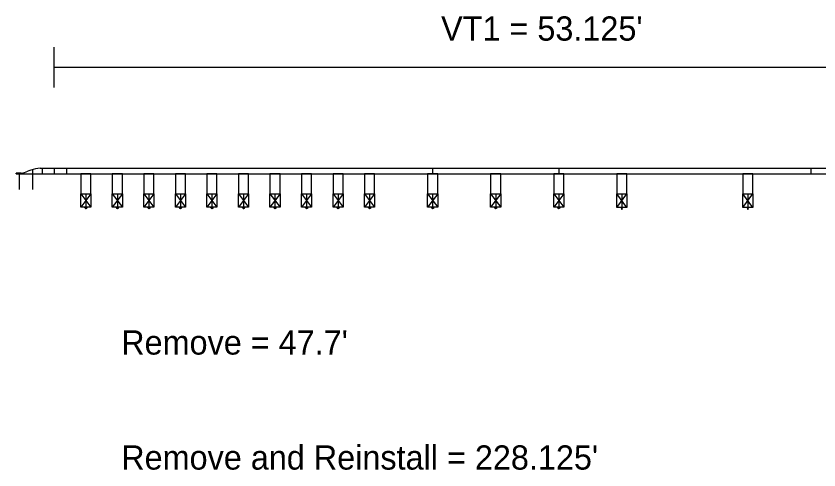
# Model space of a CAD drawing. Extents: x 16537443 to 16538473, y 7054586 to 7055469.
# Drawn here: x 16538169.69 to 16538209.48, y 7055402.88 to 7055425.37 of the extents above; entities that cross this region are included whole.
import ezdxf

# ---------------------------------------------------------------- set-up
doc = ezdxf.new("R2010")
doc.units = 0
doc.layers.add('Draft_DNC', color=7, linetype='Continuous')

msp = doc.modelspace()

# ---------------------------------------------------------------- linework, layer by layer
at = {"layer": 'Draft_DNC'}
for p, q in [((16538171.587, 7055421.832), (16538171.587, 7055423.832)), ((16538171.587, 7055422.832), (16538224.712, 7055422.833)), ((16538169.941, 7055417.587), (16538169.691, 7055417.587)), ((16538169.691, 7055417.561), (16538169.691, 7055417.587)), ((16538169.691, 7055417.561), (16538209.087, 7055417.561)), ((16538169.857, 7055416.77), (16538169.857, 7055417.588)), ((16538170.424, 7055417.739), (16538170.281, 7055417.683)), ((16538170.524, 7055416.77), (16538170.524, 7055417.772)), ((16538170.886, 7055417.832), (16538209.087, 7055417.832)), ((16538170.982, 7055417.832), (16538196.587, 7055417.832)), ((16538170.982, 7055417.832), (16538170.982, 7055417.561)), ((16538171.587, 7055417.832), (16538171.587, 7055417.561)), ((16538172.191, 7055417.832), (16538172.191, 7055417.561)), ((16538173.399, 7055417.561), (16538172.899, 7055417.561)), ((16538172.899, 7055417.561), (16538172.899, 7055416.562)), ((16538173.399, 7055416.562), (16538173.399, 7055417.561)), ((16538174.962, 7055417.561), (16538174.462, 7055417.561)), ((16538174.462, 7055417.561), (16538174.462, 7055416.562)), ((16538174.962, 7055416.562), (16538174.962, 7055417.561)), ((16538176.524, 7055417.561), (16538176.024, 7055417.561)), ((16538176.024, 7055417.561), (16538176.024, 7055416.562)), ((16538176.524, 7055416.562), (16538176.524, 7055417.561)), ((16538178.087, 7055417.561), (16538177.587, 7055417.561)), ((16538177.587, 7055417.561), (16538177.587, 7055416.562)), ((16538178.087, 7055416.562), (16538178.087, 7055417.561)), ((16538179.649, 7055417.561), (16538179.149, 7055417.561)), ((16538179.149, 7055417.561), (16538179.149, 7055416.562)), ((16538179.649, 7055416.562), (16538179.649, 7055417.561)), ((16538181.212, 7055417.561), (16538180.712, 7055417.561)), ((16538180.712, 7055417.561), (16538180.712, 7055416.562)), ((16538181.212, 7055416.562), (16538181.212, 7055417.561)), ((16538182.774, 7055417.561), (16538182.274, 7055417.561)), ((16538182.274, 7055417.561), (16538182.274, 7055416.562)), ((16538182.774, 7055416.562), (16538182.774, 7055417.561)), ((16538184.337, 7055417.561), (16538183.837, 7055417.561)), ((16538183.837, 7055417.561), (16538183.837, 7055416.562)), ((16538184.337, 7055417.561), (16538183.837, 7055417.561)), ((16538183.837, 7055417.561), (16538183.837, 7055416.562)), ((16538184.337, 7055416.562), (16538184.337, 7055417.561)), ((16538184.337, 7055416.562), (16538184.337, 7055417.561)), ((16538185.899, 7055417.561), (16538185.399, 7055417.561)), ((16538185.399, 7055417.561), (16538185.399, 7055416.562)), ((16538185.899, 7055416.562), (16538185.899, 7055417.561)), ((16538187.462, 7055417.561), (16538186.962, 7055417.561)), ((16538186.962, 7055417.561), (16538186.962, 7055416.562)), ((16538187.462, 7055416.562), (16538187.462, 7055417.561)), ((16538190.587, 7055417.561), (16538190.087, 7055417.561)), ((16538190.087, 7055417.561), (16538190.087, 7055416.562)), ((16538190.337, 7055417.832), (16538190.337, 7055417.561)), ((16538190.587, 7055416.562), (16538190.587, 7055417.561)), ((16538193.712, 7055417.561), (16538193.212, 7055417.561)), ((16538193.212, 7055417.561), (16538193.212, 7055416.562)), ((16538193.712, 7055416.562), (16538193.712, 7055417.561)), ((16538196.837, 7055417.561), (16538196.337, 7055417.561)), ((16538196.337, 7055417.561), (16538196.337, 7055416.562)), ((16538196.587, 7055417.832), (16538196.587, 7055417.561)), ((16538196.837, 7055416.562), (16538196.837, 7055417.561)), ((16538199.962, 7055417.561), (16538199.462, 7055417.561)), ((16538199.462, 7055417.561), (16538199.462, 7055416.561)), ((16538199.962, 7055416.561), (16538199.962, 7055417.561)), ((16538206.212, 7055417.561), (16538205.712, 7055417.561)), ((16538205.712, 7055417.561), (16538205.712, 7055416.561)), ((16538206.212, 7055416.561), (16538206.212, 7055417.561)), ((16538209.087, 7055417.832), (16538209.087, 7055417.561)), ((16538209.087, 7055417.832), (16538221.587, 7055417.832)), ((16538209.087, 7055417.832), (16538209.087, 7055417.561)), ((16538209.087, 7055417.561), (16538221.587, 7055417.561)), ((16538172.899, 7055416.562), (16538173.399, 7055416.562)), ((16538173.399, 7055416.562), (16538172.899, 7055415.895)), ((16538172.899, 7055416.562), (16538173.399, 7055415.895)), ((16538173.149, 7055416.562), (16538173.149, 7055415.895)), ((16538174.462, 7055416.562), (16538174.962, 7055416.562)), ((16538174.962, 7055416.562), (16538174.462, 7055415.895)), ((16538174.462, 7055416.562), (16538174.962, 7055415.895)), ((16538174.712, 7055416.562), (16538174.712, 7055415.895)), ((16538176.024, 7055416.562), (16538176.524, 7055416.562)), ((16538176.524, 7055416.562), (16538176.024, 7055415.895)), ((16538176.024, 7055416.562), (16538176.524, 7055415.895)), ((16538176.274, 7055416.562), (16538176.274, 7055415.895)), ((16538177.587, 7055416.562), (16538178.087, 7055416.562)), ((16538178.087, 7055416.562), (16538177.587, 7055415.895)), ((16538177.587, 7055416.562), (16538178.087, 7055415.895)), ((16538177.837, 7055416.562), (16538177.837, 7055415.895)), ((16538179.149, 7055416.562), (16538179.649, 7055416.562)), ((16538179.649, 7055416.562), (16538179.149, 7055415.895)), ((16538179.149, 7055416.562), (16538179.649, 7055415.895)), ((16538179.399, 7055416.562), (16538179.399, 7055415.895)), ((16538180.712, 7055416.562), (16538181.212, 7055416.562)), ((16538181.212, 7055416.562), (16538180.712, 7055415.895)), ((16538180.712, 7055416.562), (16538181.212, 7055415.895)), ((16538180.962, 7055416.562), (16538180.962, 7055415.895)), ((16538182.274, 7055416.562), (16538182.774, 7055416.562)), ((16538182.774, 7055416.562), (16538182.274, 7055415.895)), ((16538182.274, 7055416.562), (16538182.774, 7055415.895)), ((16538182.524, 7055416.562), (16538182.524, 7055415.895)), ((16538183.837, 7055416.562), (16538184.337, 7055416.562)), ((16538183.837, 7055416.562), (16538184.337, 7055416.562)), ((16538184.337, 7055416.562), (16538183.837, 7055415.895)), ((16538183.837, 7055416.562), (16538184.337, 7055415.895)), ((16538184.087, 7055416.562), (16538184.087, 7055415.895)), ((16538185.399, 7055416.562), (16538185.899, 7055416.562)), ((16538185.899, 7055416.562), (16538185.399, 7055415.895)), ((16538185.399, 7055416.562), (16538185.899, 7055415.895)), ((16538185.649, 7055416.562), (16538185.649, 7055415.895)), ((16538186.962, 7055416.562), (16538187.462, 7055416.562)), ((16538187.462, 7055416.562), (16538186.962, 7055415.895)), ((16538186.962, 7055416.562), (16538187.462, 7055415.895)), ((16538187.212, 7055416.562), (16538187.212, 7055415.895)), ((16538190.087, 7055416.562), (16538190.587, 7055416.562)), ((16538190.587, 7055416.562), (16538190.087, 7055415.895)), ((16538190.087, 7055416.562), (16538190.587, 7055415.895)), ((16538190.337, 7055416.562), (16538190.337, 7055415.895)), ((16538193.212, 7055416.562), (16538193.712, 7055416.562)), ((16538193.712, 7055416.562), (16538193.212, 7055415.895)), ((16538193.212, 7055416.562), (16538193.712, 7055415.895)), ((16538193.462, 7055416.562), (16538193.462, 7055415.895)), ((16538196.337, 7055416.562), (16538196.837, 7055416.562)), ((16538196.837, 7055416.562), (16538196.337, 7055415.895)), ((16538196.337, 7055416.562), (16538196.837, 7055415.895)), ((16538196.587, 7055416.562), (16538196.587, 7055415.895)), ((16538199.462, 7055416.561), (16538199.962, 7055416.561)), ((16538199.462, 7055415.894), (16538199.962, 7055416.561)), ((16538199.962, 7055415.894), (16538199.462, 7055416.561)), ((16538199.712, 7055416.561), (16538199.712, 7055415.894)), ((16538205.712, 7055416.561), (16538206.212, 7055416.561)), ((16538205.712, 7055415.894), (16538206.212, 7055416.561)), ((16538206.212, 7055415.894), (16538205.712, 7055416.561)), ((16538205.962, 7055416.561), (16538205.962, 7055415.894)), ((16538173.399, 7055415.895), (16538172.899, 7055415.895)), ((16538173.069, 7055415.895), (16538173.069, 7055415.879)), ((16538173.229, 7055415.895), (16538173.229, 7055415.879)), ((16538174.962, 7055415.895), (16538174.462, 7055415.895)), ((16538174.632, 7055415.895), (16538174.632, 7055415.879)), ((16538174.792, 7055415.895), (16538174.792, 7055415.879)), ((16538176.524, 7055415.895), (16538176.024, 7055415.895)), ((16538176.194, 7055415.895), (16538176.194, 7055415.879)), ((16538176.354, 7055415.895), (16538176.354, 7055415.879)), ((16538178.087, 7055415.895), (16538177.587, 7055415.895)), ((16538177.757, 7055415.895), (16538177.757, 7055415.879)), ((16538177.917, 7055415.895), (16538177.917, 7055415.879)), ((16538179.649, 7055415.895), (16538179.149, 7055415.895)), ((16538179.319, 7055415.895), (16538179.319, 7055415.879)), ((16538179.479, 7055415.895), (16538179.479, 7055415.879)), ((16538181.212, 7055415.895), (16538180.712, 7055415.895)), ((16538180.882, 7055415.895), (16538180.882, 7055415.879)), ((16538181.042, 7055415.895), (16538181.042, 7055415.879)), ((16538182.774, 7055415.895), (16538182.274, 7055415.895)), ((16538182.444, 7055415.895), (16538182.444, 7055415.879)), ((16538182.604, 7055415.895), (16538182.604, 7055415.879)), ((16538184.337, 7055415.895), (16538183.837, 7055415.895)), ((16538184.007, 7055415.895), (16538184.007, 7055415.879)), ((16538184.167, 7055415.895), (16538184.167, 7055415.879)), ((16538185.899, 7055415.895), (16538185.399, 7055415.895)), ((16538185.569, 7055415.895), (16538185.569, 7055415.879)), ((16538185.729, 7055415.895), (16538185.729, 7055415.879)), ((16538187.462, 7055415.895), (16538186.962, 7055415.895)), ((16538187.132, 7055415.895), (16538187.132, 7055415.879)), ((16538187.292, 7055415.895), (16538187.292, 7055415.879)), ((16538190.587, 7055415.895), (16538190.087, 7055415.895)), ((16538190.257, 7055415.895), (16538190.257, 7055415.879)), ((16538190.417, 7055415.895), (16538190.417, 7055415.879)), ((16538193.712, 7055415.895), (16538193.212, 7055415.895)), ((16538193.382, 7055415.895), (16538193.382, 7055415.879)), ((16538193.542, 7055415.895), (16538193.542, 7055415.879)), ((16538196.837, 7055415.895), (16538196.337, 7055415.895)), ((16538196.507, 7055415.895), (16538196.507, 7055415.879)), ((16538196.667, 7055415.895), (16538196.667, 7055415.879)), ((16538173.229, 7055415.879), (16538173.069, 7055415.879)), ((16538173.109, 7055415.879), (16538173.109, 7055415.841)), ((16538173.189, 7055415.841), (16538173.109, 7055415.841)), ((16538173.125, 7055415.879), (16538173.125, 7055415.841)), ((16538173.139, 7055415.841), (16538173.139, 7055415.812)), ((16538173.159, 7055415.812), (16538173.139, 7055415.812)), ((16538173.159, 7055415.841), (16538173.159, 7055415.812)), ((16538173.173, 7055415.879), (16538173.173, 7055415.841)), ((16538173.189, 7055415.879), (16538173.189, 7055415.841)), ((16538174.792, 7055415.879), (16538174.632, 7055415.879)), ((16538174.672, 7055415.879), (16538174.672, 7055415.841)), ((16538174.752, 7055415.841), (16538174.672, 7055415.841)), ((16538174.688, 7055415.879), (16538174.688, 7055415.841)), ((16538174.702, 7055415.841), (16538174.702, 7055415.812)), ((16538174.722, 7055415.812), (16538174.702, 7055415.812)), ((16538174.722, 7055415.841), (16538174.722, 7055415.812)), ((16538174.736, 7055415.879), (16538174.736, 7055415.841)), ((16538174.752, 7055415.879), (16538174.752, 7055415.841)), ((16538176.354, 7055415.879), (16538176.194, 7055415.879)), ((16538176.234, 7055415.879), (16538176.234, 7055415.841)), ((16538176.314, 7055415.841), (16538176.234, 7055415.841)), ((16538176.25, 7055415.879), (16538176.25, 7055415.841)), ((16538176.264, 7055415.841), (16538176.264, 7055415.812)), ((16538176.284, 7055415.812), (16538176.264, 7055415.812)), ((16538176.284, 7055415.841), (16538176.284, 7055415.812)), ((16538176.298, 7055415.879), (16538176.298, 7055415.841)), ((16538176.314, 7055415.879), (16538176.314, 7055415.841)), ((16538177.917, 7055415.879), (16538177.757, 7055415.879)), ((16538177.797, 7055415.879), (16538177.797, 7055415.841)), ((16538177.877, 7055415.841), (16538177.797, 7055415.841)), ((16538177.813, 7055415.879), (16538177.813, 7055415.841)), ((16538177.827, 7055415.841), (16538177.827, 7055415.812)), ((16538177.847, 7055415.812), (16538177.827, 7055415.812)), ((16538177.847, 7055415.841), (16538177.847, 7055415.812)), ((16538177.861, 7055415.879), (16538177.861, 7055415.841)), ((16538177.877, 7055415.879), (16538177.877, 7055415.841)), ((16538179.479, 7055415.879), (16538179.319, 7055415.879)), ((16538179.359, 7055415.879), (16538179.359, 7055415.841)), ((16538179.439, 7055415.841), (16538179.359, 7055415.841)), ((16538179.375, 7055415.879), (16538179.375, 7055415.841)), ((16538179.389, 7055415.841), (16538179.389, 7055415.812)), ((16538179.409, 7055415.812), (16538179.389, 7055415.812)), ((16538179.409, 7055415.841), (16538179.409, 7055415.812)), ((16538179.423, 7055415.879), (16538179.423, 7055415.841)), ((16538179.439, 7055415.879), (16538179.439, 7055415.841)), ((16538181.042, 7055415.879), (16538180.882, 7055415.879)), ((16538180.922, 7055415.879), (16538180.922, 7055415.841)), ((16538181.002, 7055415.841), (16538180.922, 7055415.841)), ((16538180.938, 7055415.879), (16538180.938, 7055415.841)), ((16538180.952, 7055415.841), (16538180.952, 7055415.812)), ((16538180.972, 7055415.812), (16538180.952, 7055415.812)), ((16538180.972, 7055415.841), (16538180.972, 7055415.812)), ((16538180.986, 7055415.879), (16538180.986, 7055415.841)), ((16538181.002, 7055415.879), (16538181.002, 7055415.841)), ((16538182.604, 7055415.879), (16538182.444, 7055415.879)), ((16538182.484, 7055415.879), (16538182.484, 7055415.841)), ((16538182.564, 7055415.841), (16538182.484, 7055415.841)), ((16538182.5, 7055415.879), (16538182.5, 7055415.841)), ((16538182.514, 7055415.841), (16538182.514, 7055415.812)), ((16538182.534, 7055415.812), (16538182.514, 7055415.812)), ((16538182.534, 7055415.841), (16538182.534, 7055415.812)), ((16538182.548, 7055415.879), (16538182.548, 7055415.841)), ((16538182.564, 7055415.879), (16538182.564, 7055415.841)), ((16538184.167, 7055415.879), (16538184.007, 7055415.879)), ((16538184.047, 7055415.879), (16538184.047, 7055415.841)), ((16538184.127, 7055415.841), (16538184.047, 7055415.841)), ((16538184.063, 7055415.879), (16538184.063, 7055415.841)), ((16538184.077, 7055415.841), (16538184.077, 7055415.812)), ((16538184.097, 7055415.812), (16538184.077, 7055415.812)), ((16538184.097, 7055415.841), (16538184.097, 7055415.812)), ((16538184.111, 7055415.879), (16538184.111, 7055415.841)), ((16538184.127, 7055415.879), (16538184.127, 7055415.841)), ((16538185.729, 7055415.879), (16538185.569, 7055415.879)), ((16538185.609, 7055415.879), (16538185.609, 7055415.841)), ((16538185.689, 7055415.841), (16538185.609, 7055415.841)), ((16538185.625, 7055415.879), (16538185.625, 7055415.841)), ((16538185.639, 7055415.841), (16538185.639, 7055415.812)), ((16538185.659, 7055415.812), (16538185.639, 7055415.812)), ((16538185.659, 7055415.841), (16538185.659, 7055415.812)), ((16538185.673, 7055415.879), (16538185.673, 7055415.841)), ((16538185.689, 7055415.879), (16538185.689, 7055415.841)), ((16538187.292, 7055415.879), (16538187.132, 7055415.879)), ((16538187.172, 7055415.879), (16538187.172, 7055415.841)), ((16538187.252, 7055415.841), (16538187.172, 7055415.841)), ((16538187.188, 7055415.879), (16538187.188, 7055415.841)), ((16538187.202, 7055415.841), (16538187.202, 7055415.812)), ((16538187.222, 7055415.812), (16538187.202, 7055415.812)), ((16538187.222, 7055415.841), (16538187.222, 7055415.812)), ((16538187.236, 7055415.879), (16538187.236, 7055415.841)), ((16538187.252, 7055415.879), (16538187.252, 7055415.841)), ((16538190.417, 7055415.879), (16538190.257, 7055415.879)), ((16538190.297, 7055415.879), (16538190.297, 7055415.841)), ((16538190.377, 7055415.841), (16538190.297, 7055415.841)), ((16538190.313, 7055415.879), (16538190.313, 7055415.841)), ((16538190.327, 7055415.841), (16538190.327, 7055415.812)), ((16538190.347, 7055415.812), (16538190.327, 7055415.812)), ((16538190.347, 7055415.841), (16538190.347, 7055415.812)), ((16538190.361, 7055415.879), (16538190.361, 7055415.841)), ((16538190.377, 7055415.879), (16538190.377, 7055415.841)), ((16538193.542, 7055415.879), (16538193.382, 7055415.879)), ((16538193.422, 7055415.879), (16538193.422, 7055415.841)), ((16538193.502, 7055415.841), (16538193.422, 7055415.841)), ((16538193.438, 7055415.879), (16538193.438, 7055415.841)), ((16538193.452, 7055415.841), (16538193.452, 7055415.812)), ((16538193.472, 7055415.812), (16538193.452, 7055415.812)), ((16538193.472, 7055415.841), (16538193.472, 7055415.812)), ((16538193.486, 7055415.879), (16538193.486, 7055415.841)), ((16538193.502, 7055415.879), (16538193.502, 7055415.841)), ((16538196.667, 7055415.879), (16538196.507, 7055415.879)), ((16538196.547, 7055415.879), (16538196.547, 7055415.841)), ((16538196.627, 7055415.841), (16538196.547, 7055415.841)), ((16538196.563, 7055415.879), (16538196.563, 7055415.841)), ((16538196.577, 7055415.841), (16538196.577, 7055415.812)), ((16538196.597, 7055415.812), (16538196.577, 7055415.812)), ((16538196.597, 7055415.841), (16538196.597, 7055415.812)), ((16538196.611, 7055415.879), (16538196.611, 7055415.841)), ((16538196.627, 7055415.879), (16538196.627, 7055415.841)), ((16538199.712, 7055415.797), (16538199.712, 7055415.79)), ((16538205.962, 7055415.797), (16538205.962, 7055415.79))]:
    msp.add_line(p, q, dxfattribs=at)
for points in [[(16538172.899, 7055416.562), (16538173.399, 7055416.562), (16538173.399, 7055415.895), (16538172.899, 7055415.895)], [(16538174.462, 7055416.562), (16538174.962, 7055416.562), (16538174.962, 7055415.895), (16538174.462, 7055415.895)], [(16538176.024, 7055416.562), (16538176.524, 7055416.562), (16538176.524, 7055415.895), (16538176.024, 7055415.895)], [(16538177.587, 7055416.562), (16538178.087, 7055416.562), (16538178.087, 7055415.895), (16538177.587, 7055415.895)], [(16538179.149, 7055416.562), (16538179.649, 7055416.562), (16538179.649, 7055415.895), (16538179.149, 7055415.895)], [(16538180.712, 7055416.562), (16538181.212, 7055416.562), (16538181.212, 7055415.895), (16538180.712, 7055415.895)], [(16538182.274, 7055416.562), (16538182.774, 7055416.562), (16538182.774, 7055415.895), (16538182.274, 7055415.895)], [(16538183.837, 7055416.562), (16538184.337, 7055416.562), (16538184.337, 7055415.895), (16538183.837, 7055415.895)], [(16538185.399, 7055416.562), (16538185.899, 7055416.562), (16538185.899, 7055415.895), (16538185.399, 7055415.895)], [(16538186.962, 7055416.562), (16538187.462, 7055416.562), (16538187.462, 7055415.895), (16538186.962, 7055415.895)], [(16538190.087, 7055416.562), (16538190.587, 7055416.562), (16538190.587, 7055415.895), (16538190.087, 7055415.895)], [(16538193.212, 7055416.562), (16538193.712, 7055416.562), (16538193.712, 7055415.895), (16538193.212, 7055415.895)], [(16538196.337, 7055416.562), (16538196.837, 7055416.562), (16538196.837, 7055415.895), (16538196.337, 7055415.895)], [(16538199.462, 7055416.561), (16538199.962, 7055416.561), (16538199.962, 7055415.894), (16538199.462, 7055415.894)], [(16538205.712, 7055416.561), (16538206.212, 7055416.561), (16538206.212, 7055415.894), (16538205.712, 7055415.894)]]:
    msp.add_lwpolyline(points, close=True, dxfattribs=at)
for points in [[(16538199.678, 7055415.894), (16538199.678, 7055415.851), (16538199.745, 7055415.851), (16538199.745, 7055415.894)], [(16538205.928, 7055415.894), (16538205.928, 7055415.851), (16538205.995, 7055415.851), (16538205.995, 7055415.894)], [(16538199.692, 7055415.851), (16538199.692, 7055415.797), (16538199.731, 7055415.797), (16538199.731, 7055415.851)], [(16538205.942, 7055415.851), (16538205.942, 7055415.797), (16538205.981, 7055415.797), (16538205.981, 7055415.851)]]:
    msp.add_lwpolyline(points, dxfattribs=at)
for centre, major_axis, start_param, end_param in [((16538169.729, 7055418.91), (1.379, 0), 4.866664, 5.124351), ((16538170.966, 7055416.338), (-1.542, 0), 4.763936, 5.071137)]:
    msp.add_ellipse(centre, major_axis=major_axis, ratio=0.97085, start_param=start_param, end_param=end_param, dxfattribs=at)

# ---------------------------------------------------------------- texts
for s, p in [("VT1 = 53.125'", (16538190.755, 7055424.155)), ("Remove = 47.7'", (16538174.902, 7055408.597)), ("Remove and Reinstall = 228.125'", (16538174.903, 7055402.897))]:
    msp.add_text(s, height=1.2, rotation=0.001, dxfattribs=at).set_placement(p)

doc.saveas('drawing.dxf')
